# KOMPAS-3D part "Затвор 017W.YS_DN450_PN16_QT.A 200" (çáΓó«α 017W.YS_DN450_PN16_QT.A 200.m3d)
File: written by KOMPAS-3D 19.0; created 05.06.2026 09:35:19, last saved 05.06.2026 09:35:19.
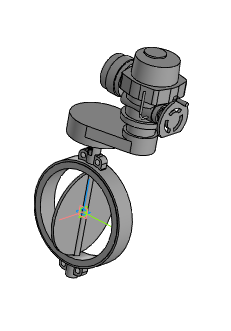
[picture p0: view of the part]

Document properties: Автор: Энергия; Полное имя файла: ..\..\..\3d для проектировщиков\x.x Тип 017W.Y(S) Затвор дисковый поворотный межфланцевый\Затвор 017W.Y(S)_DN32-DN1200_QT.A_MT903.A\Затвор 017W.YS_DN450_PN16_QT.A 200.a3d

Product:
- Part/product: Затвор 017W.YS_DN450_PN16_QT.A 200
    Масса: 314.692

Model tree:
1. Операция без истории:1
